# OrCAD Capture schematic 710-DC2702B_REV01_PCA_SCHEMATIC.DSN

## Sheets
1 PAGE1: size Custom
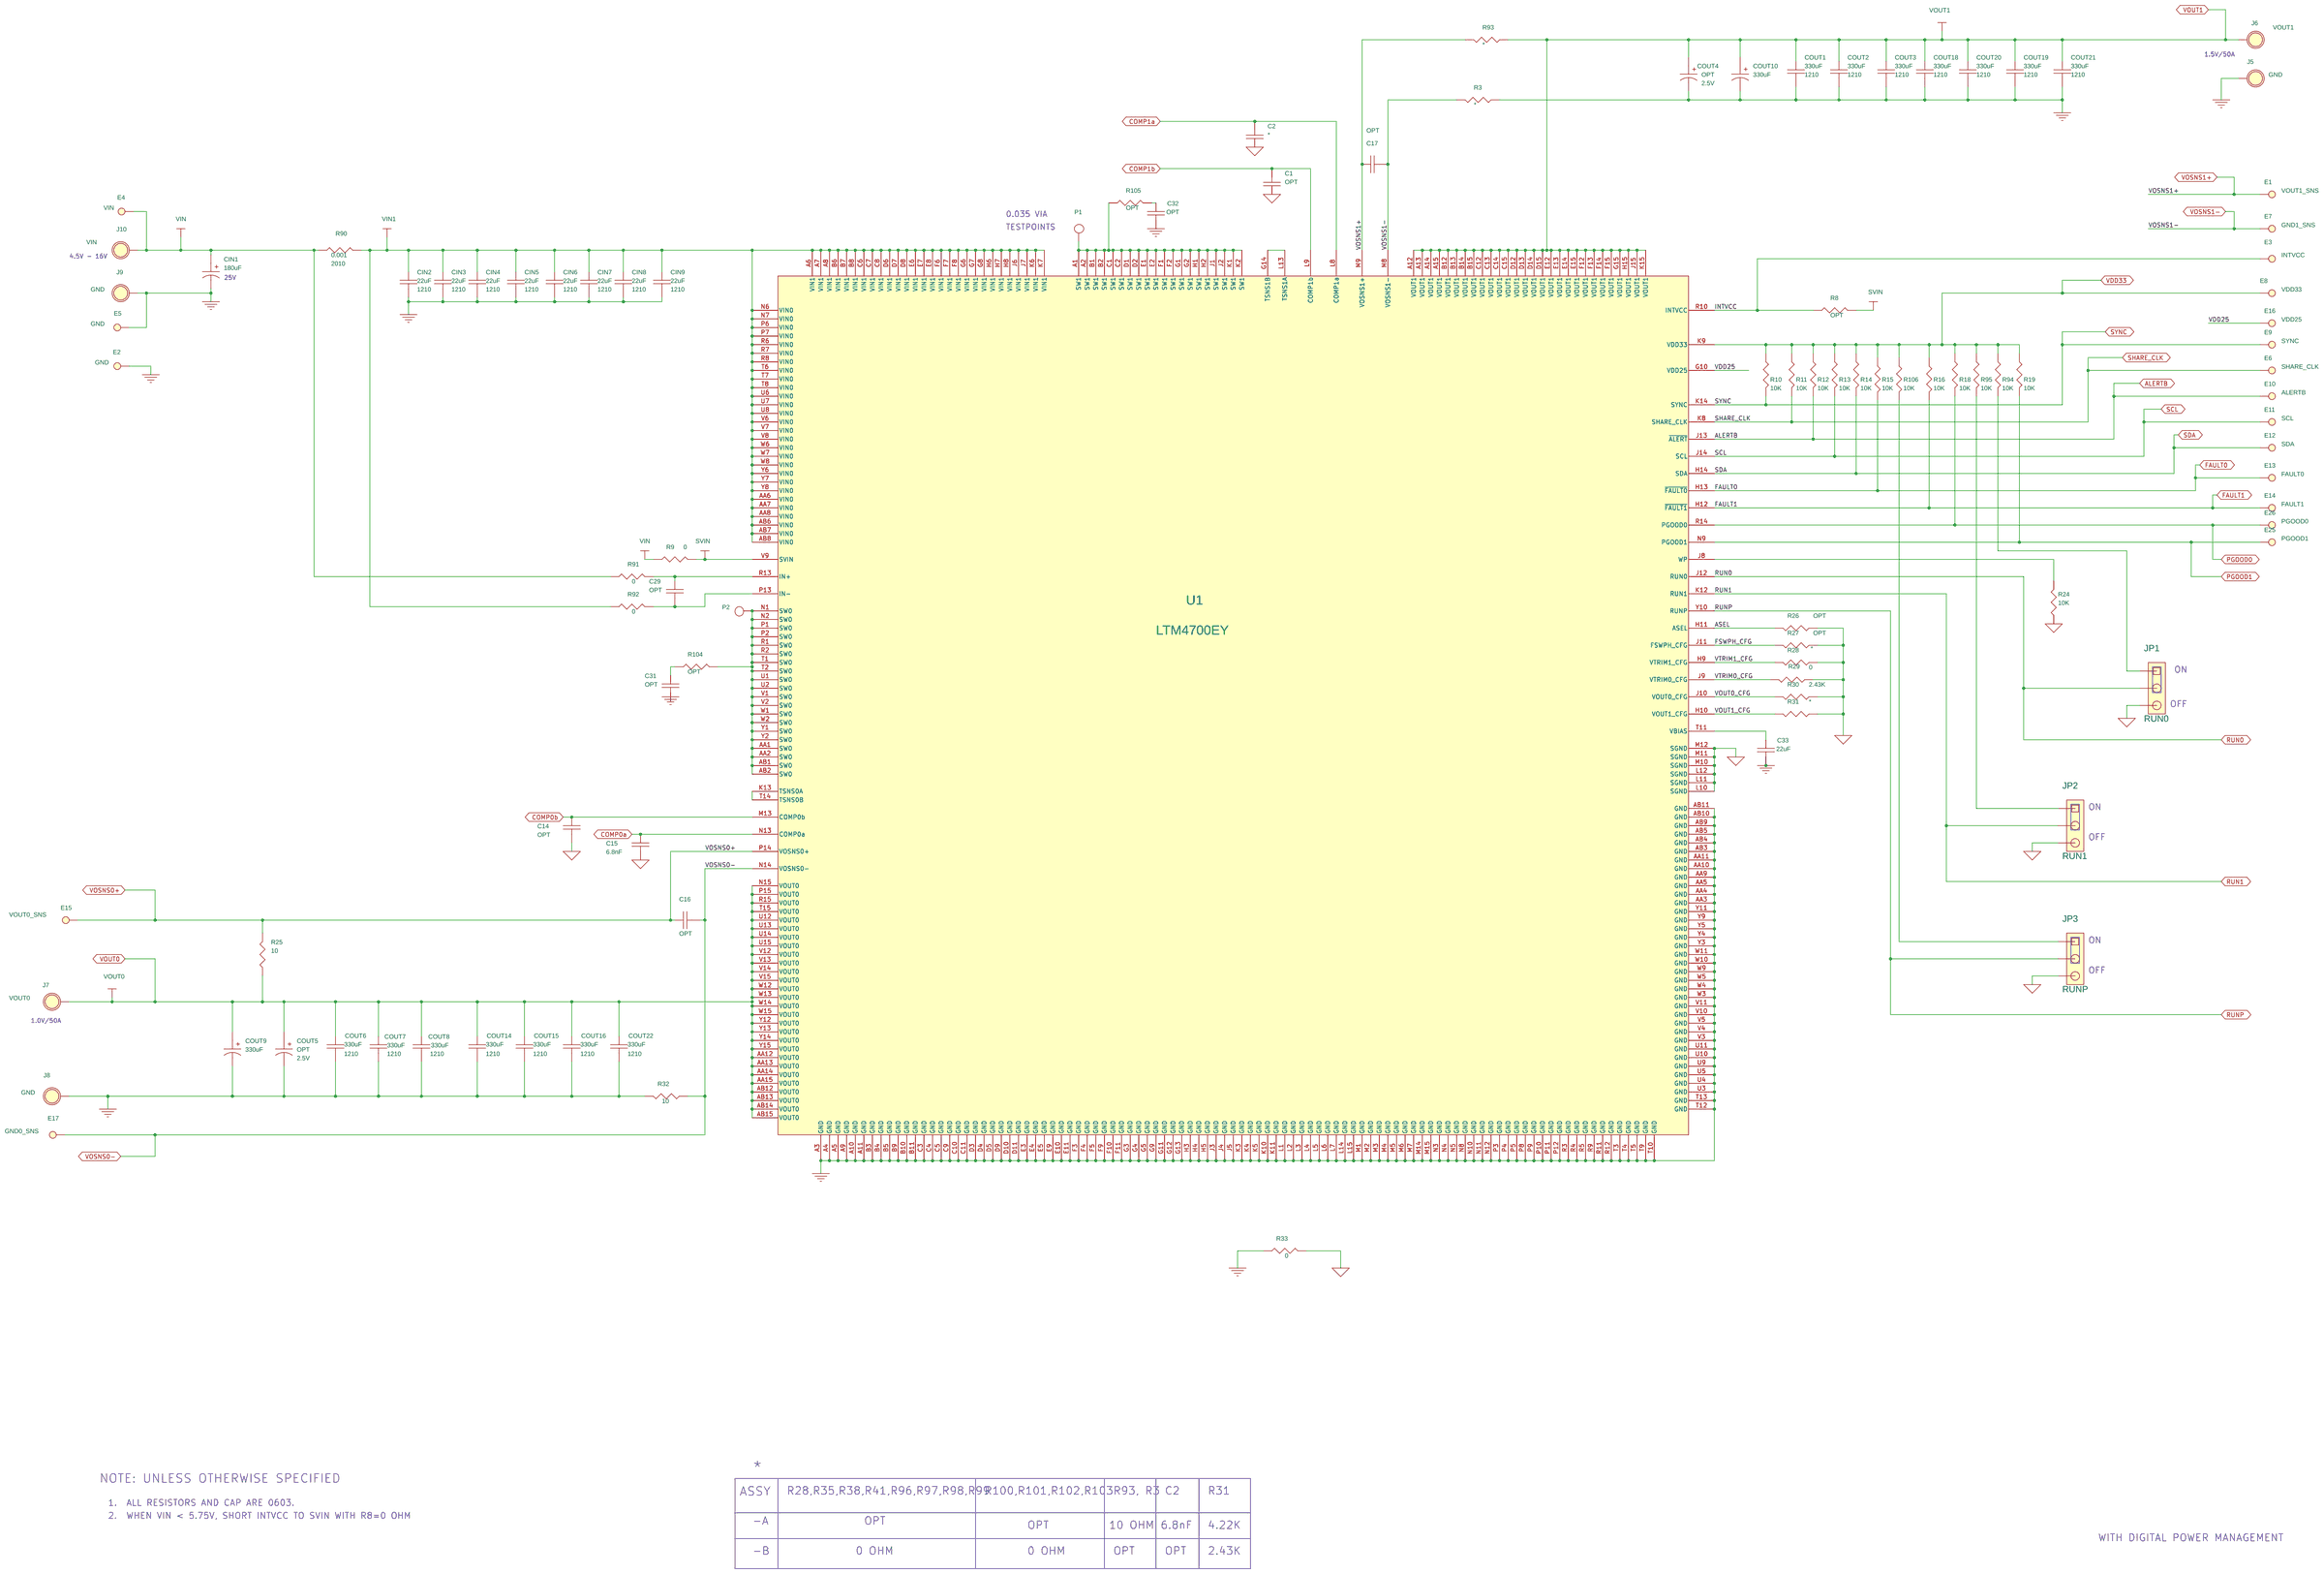
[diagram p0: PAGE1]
2 PAGE3: size B; title: CONTROLLER with GaN FET; company: ANALOG DEVICES; note: DEMO BOARD BILL OF MATERIALS; note: DUAL 50A OR SINGLE 100A uMODULE REGULATOR
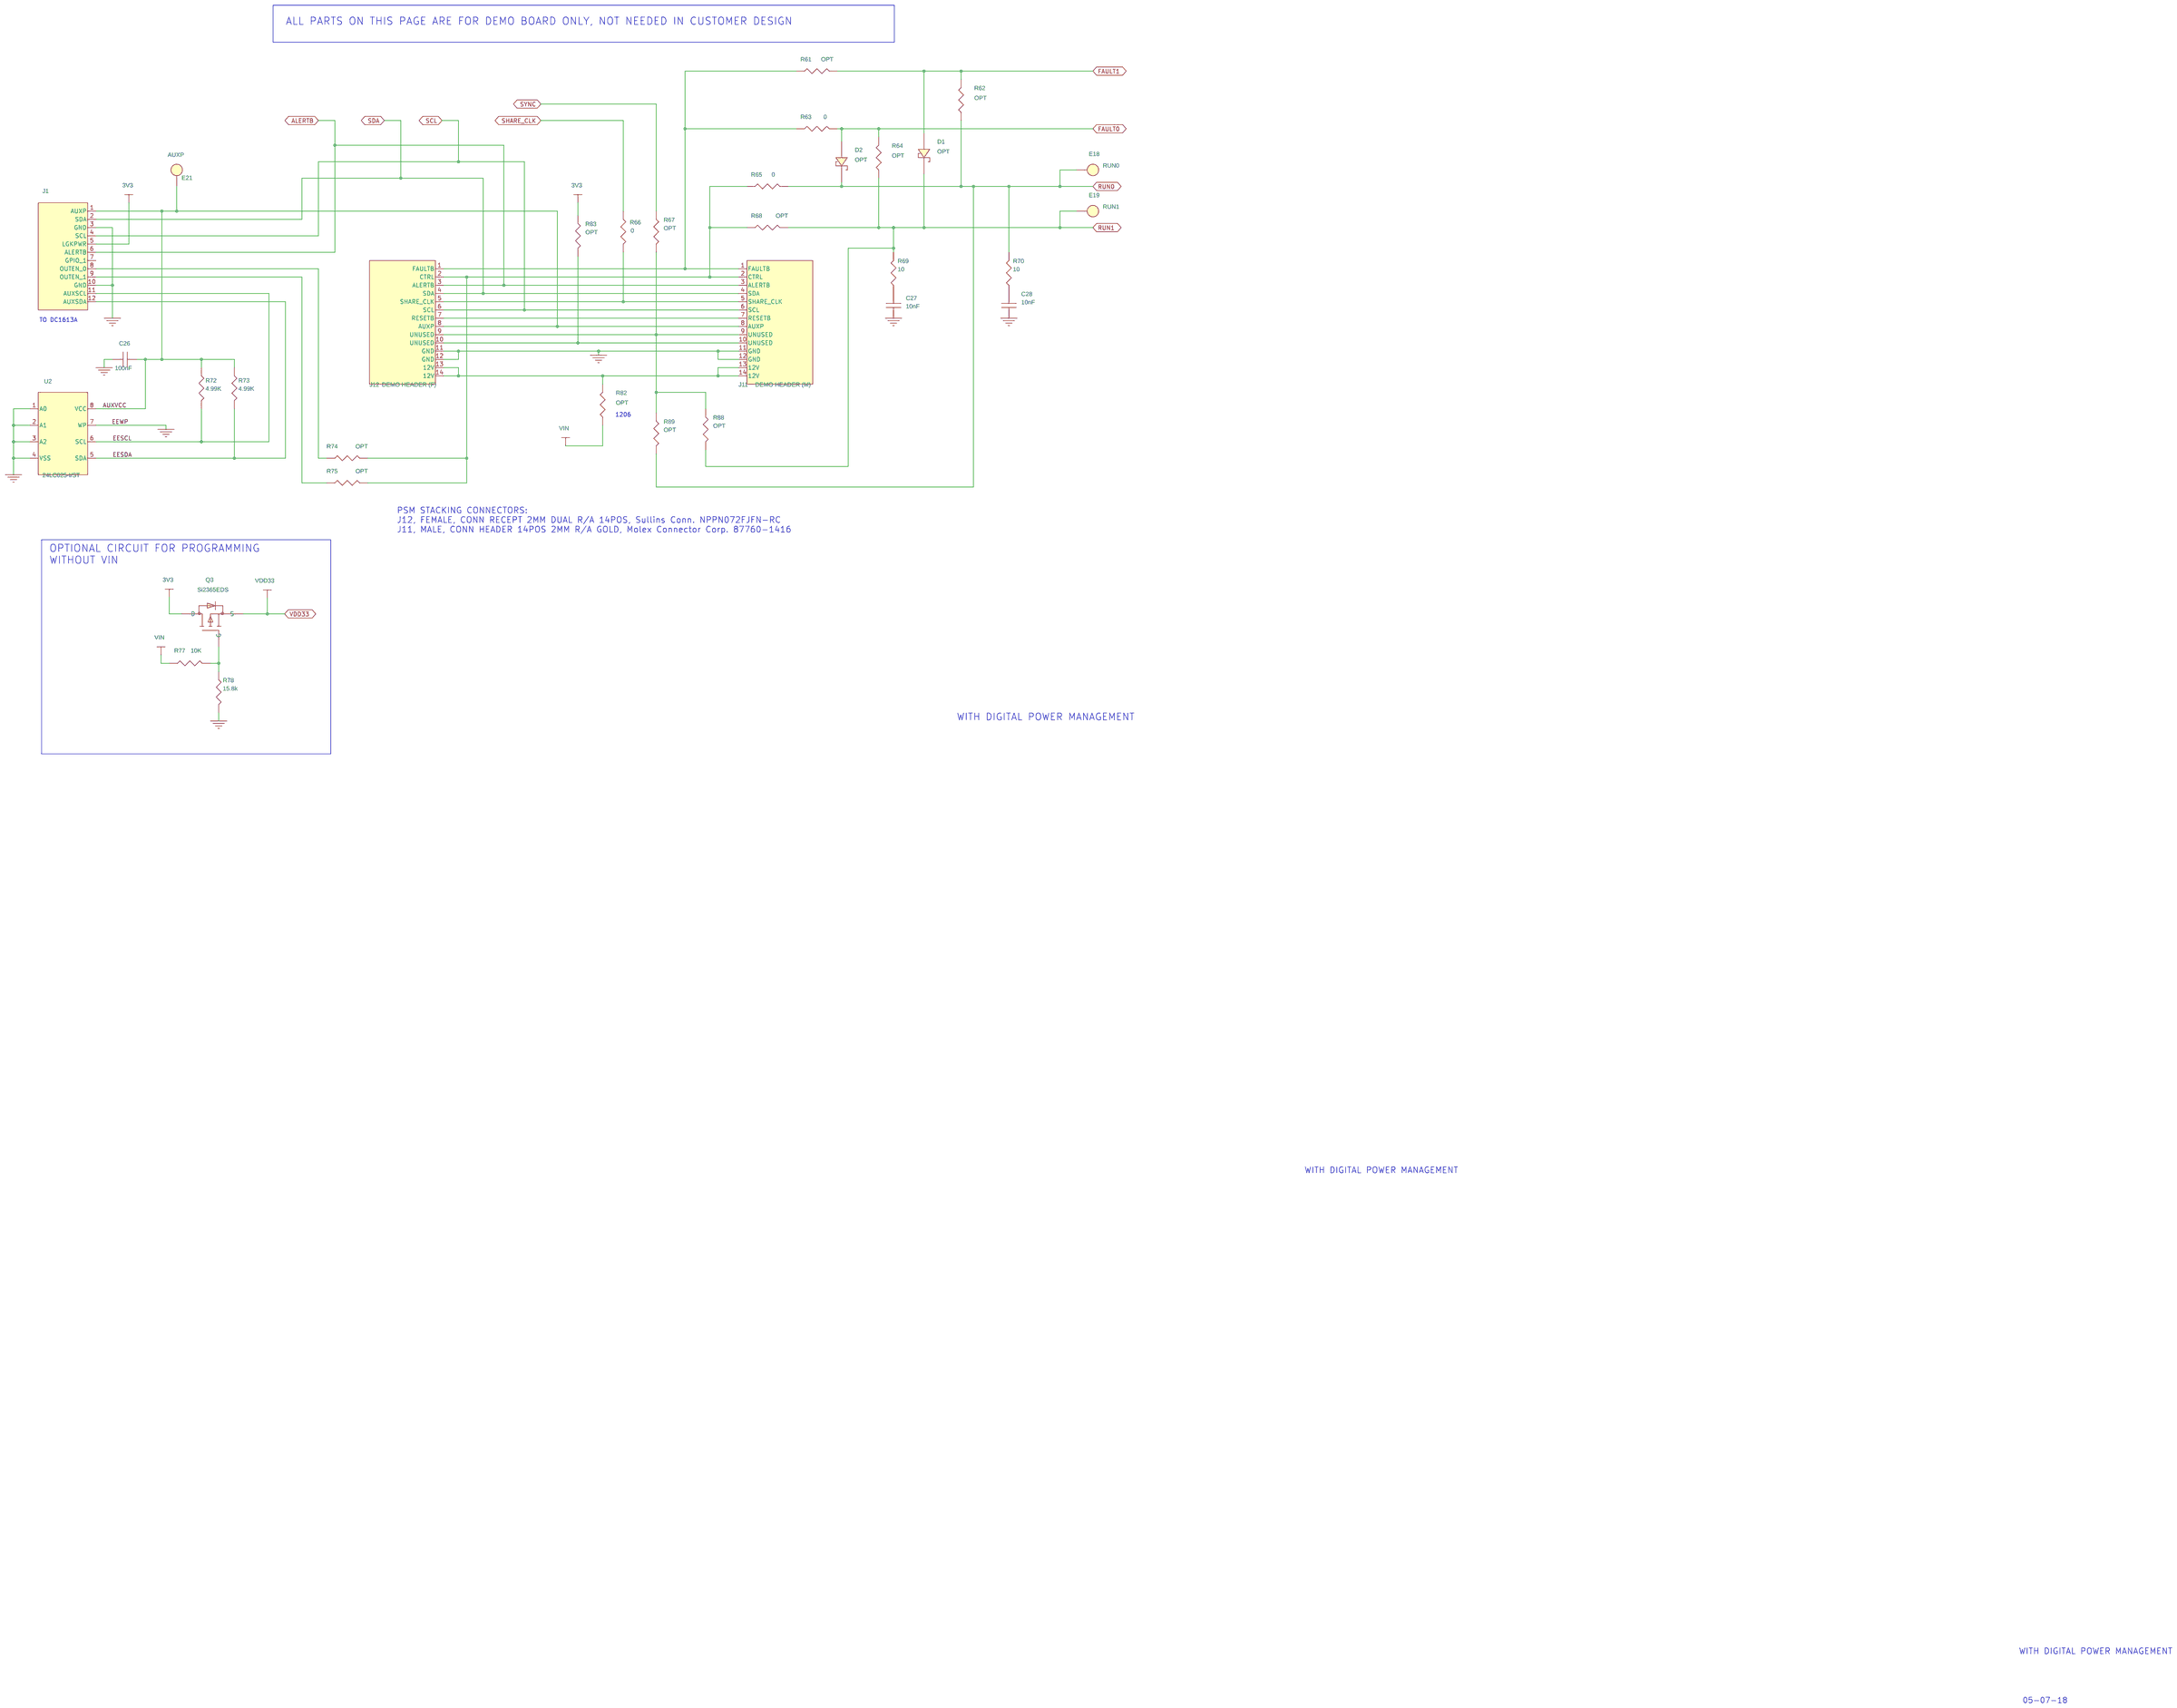
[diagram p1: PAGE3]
3 PAGE2: size Custom; title: CONTROLLER with GaN FET; company: ANALOG DEVICES; note: DEMO BOARD BILL OF MATERIALS; note: DUAL 50A OR SINGLE 100A uMODULE REGULATOR
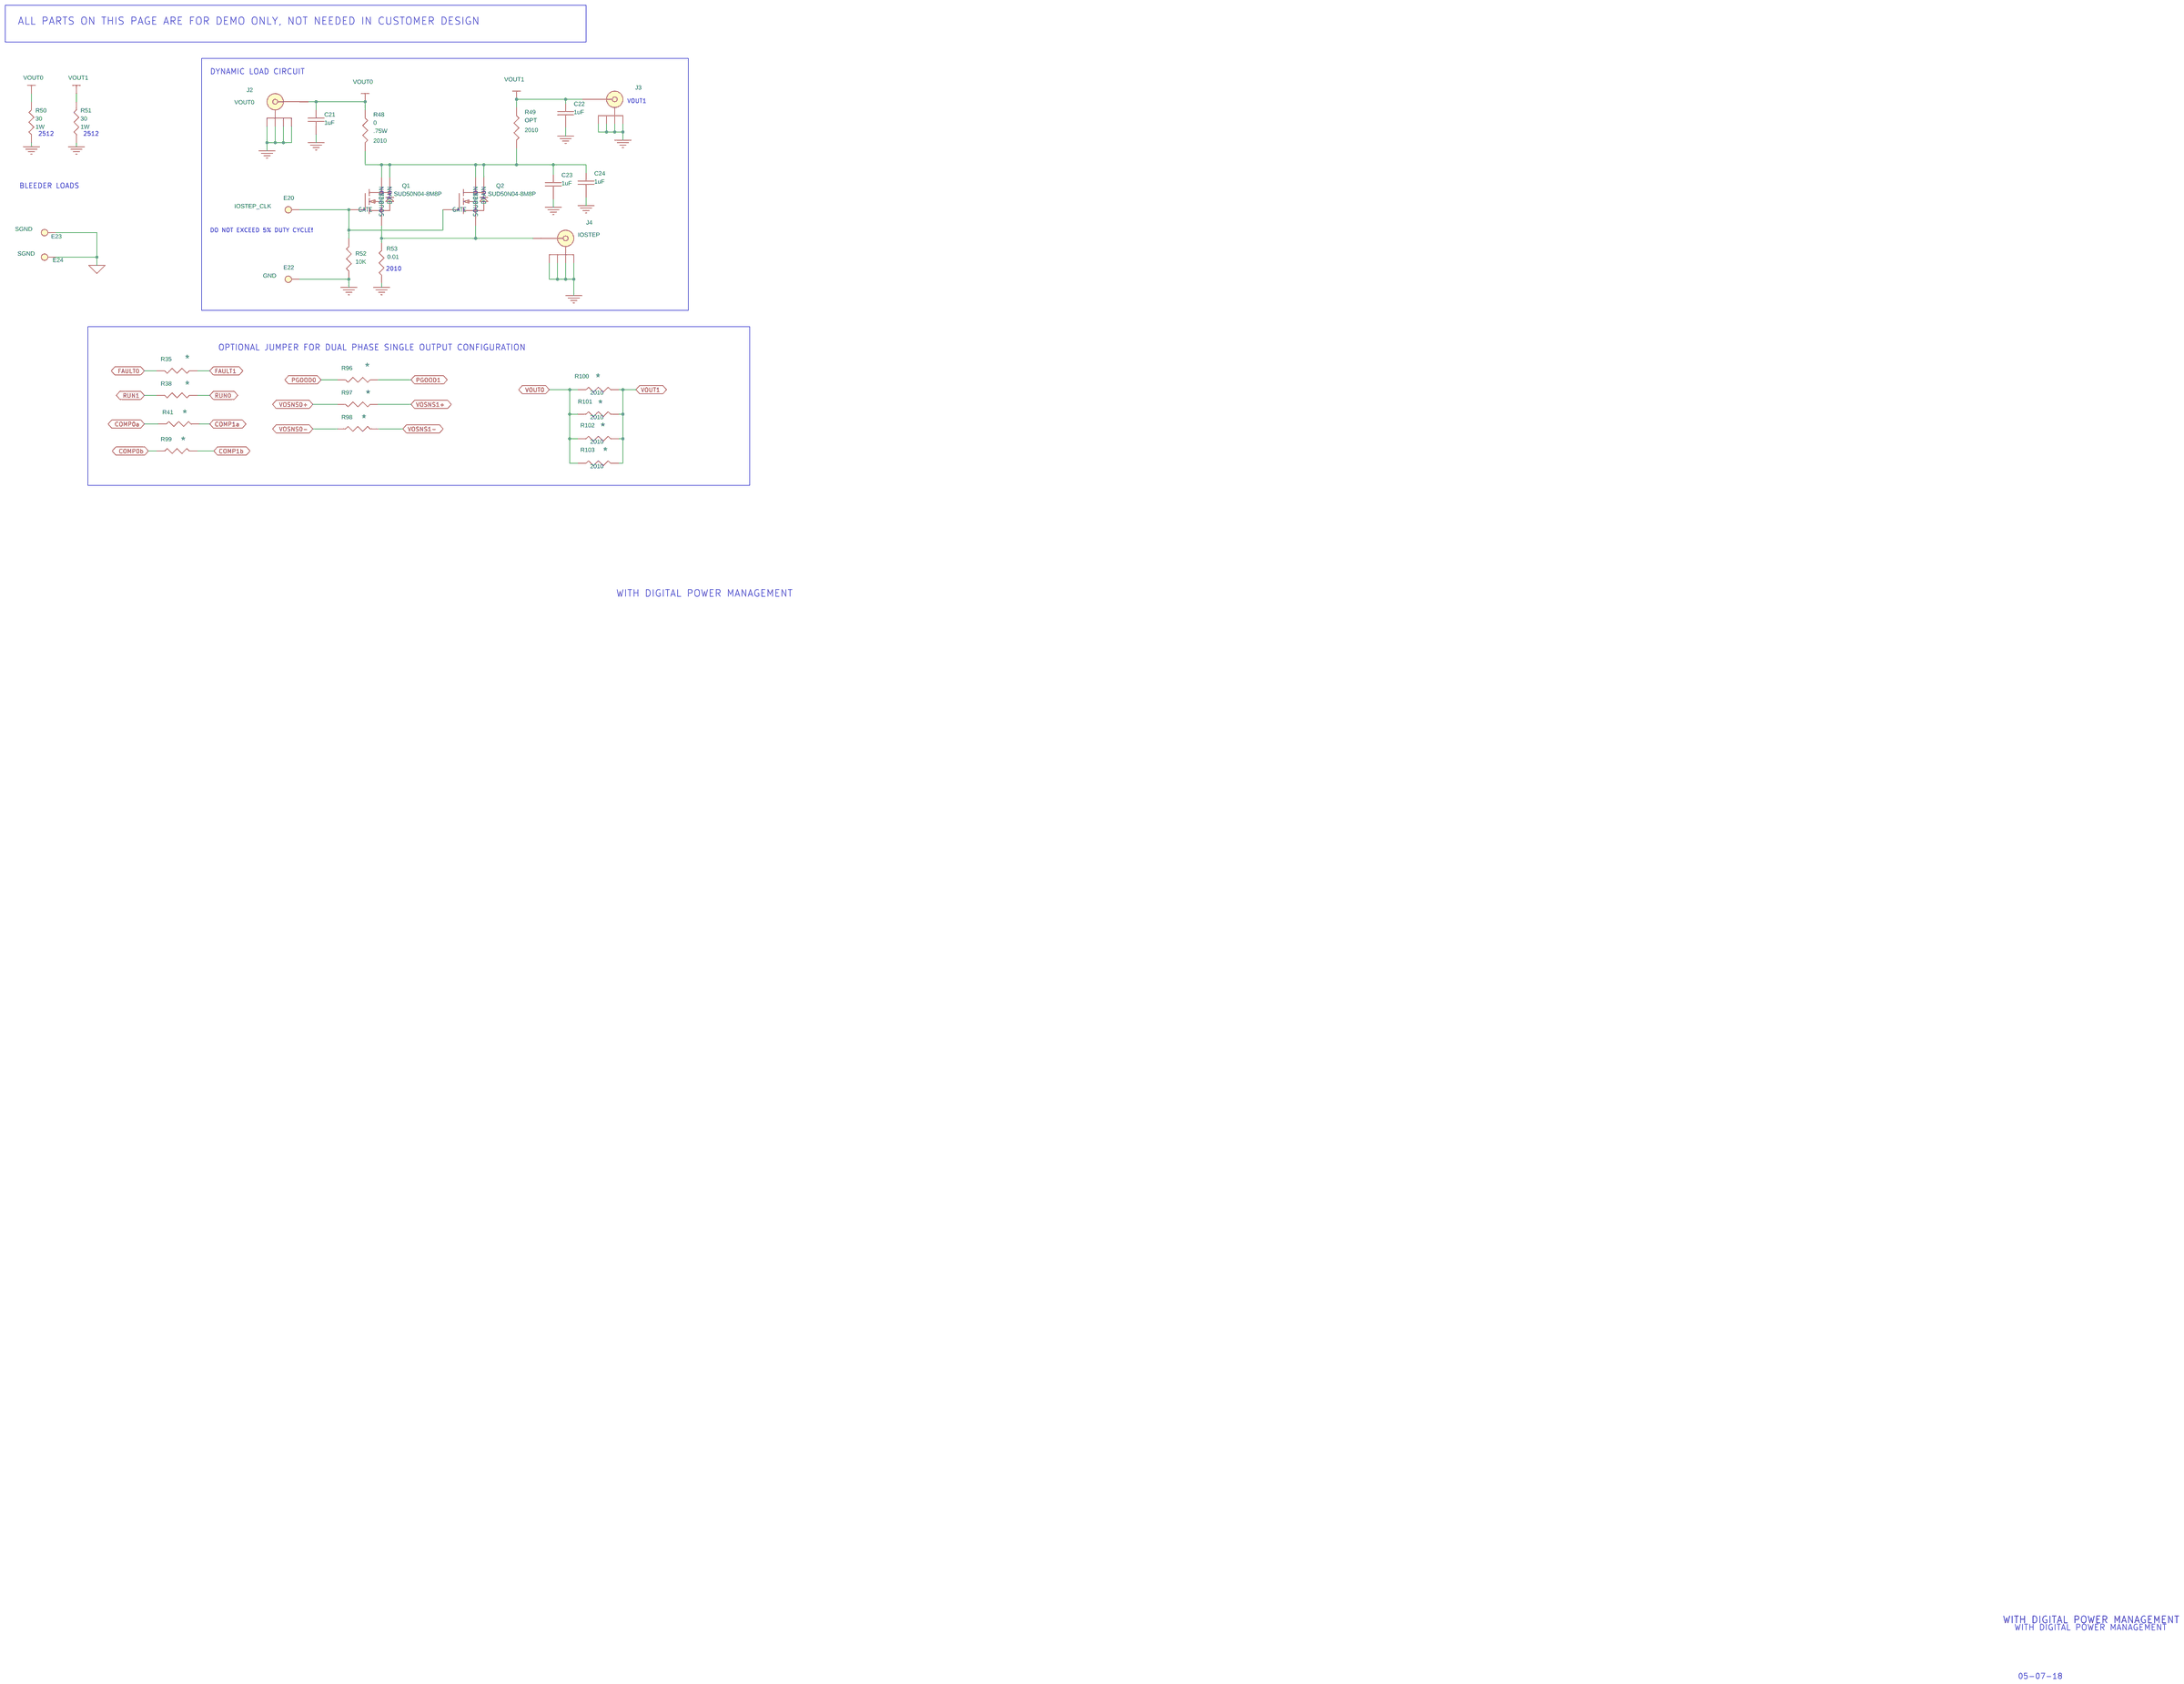
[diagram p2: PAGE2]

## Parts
sheet PAGE1
C1  OPT  [0603XS]
C2  *  [0603XS]
C14  OPT  [0603XS]
C15  6.8nF  [0603XS]
C16  OPT  [0603]
C17  OPT  [0603]
C29  OPT  [0603XS]
C31  OPT  [0603]
C32  OPT  [0603]
C33  22uF  [0603XS]
CIN1  180uF  [SANYO\8X10]
CIN2  22uF  [1210]
CIN3  22uF  [1210]
CIN4  22uF  [1210]
CIN5  22uF  [1210]
CIN6  22uF  [1210]
CIN7  22uF  [1210]
CIN8  22uF  [1210]
CIN9  22uF  [1210]
COUT1  330uF  [1210]
COUT2  330uF  [1210]
COUT3  330uF  [1210]
COUT4  OPT  [D3L]
COUT5  OPT  [D3L]
COUT6  330uF  [1210]
COUT7  330uF  [1210]
COUT8  330uF  [1210]
COUT9  330uF  [D3L]
COUT10  330uF  [D3L]
COUT14  330uF  [1210]
COUT15  330uF  [1210]
COUT16  330uF  [1210]
COUT18  330uF  [1210]
COUT19  330uF  [1210]
COUT20  330uF  [1210]
COUT21  330uF  [1210]
COUT22  330uF  [1210]
E1  TURRETS  [TURRETS]
E2  GND  [TURRETS]
E3  INTVCC  [TURRETS]
E4  TURRETS  [TURRETS]
E5  GND  [TURRETS]
E6  TURRETS  [TURRETS]
E7  TURRETS  [TURRETS]
E8  VDD33  [TURRETS]
E9  TURRETS  [TURRETS]
E10  TURRETS  [TURRETS]
E11  TURRETS  [TURRETS]
E12  TURRETS  [TURRETS]
E13  TURRETS  [TURRETS]
E14  TURRETS  [TURRETS]
E15  TURRETS  [TURRETS]
E16  VDD25  [TURRETS]
E17  TURRETS  [TURRETS]
E25  TURRETS  [TURRETS]
E26  TURRETS  [TURRETS]
J5  BANANA SMALL  [CON\LUG\10]
J6  BANANA SMALL  [CON\LUG\10]
J7  BANANA SMALL  [CON\LUG\10]
J8  BANANA SMALL  [CON\LUG\10]
J9  BANANA SMALL  [CON\LUG\10]
J10  BANANA SMALL  [CON\LUG\10]
JP1  3 Pins 2mm Ctrs.  [HD1X3-079]
JP2  3 Pins 2mm Ctrs.  [HD1X3-079]
JP3  3 Pins 2mm Ctrs.  [HD1X3-079]
P1  TURRETS  [PAD]
P2  TURRETS  [PAD]
R3  *  [0603]
R8  OPT  [0603XS]
R9  0  [0603XS]
R10  10K  [0603]
R11  10K  [0603]
R12  10K  [0603]
R13  10K  [0603]
R14  10K  [0603]
R15  10K  [0603]
R16  10K  [0603]
R18  10K  [0603]
R19  10K  [0603]
R24  10K  [0603]
R25  10  [0603]
R26  OPT  [0603]
R27  OPT  [0603]
R28  *  [0603]
R29  0  [0603]
R30  2.43K  [0603]
R31  *  [0603]
R32  10  [0603]
R33  0  [0603XS]
R90  0.001  [2010]
R91  0  [0603XS]
R92  0  [0603XS]
R93  *  [0603]
R94  10K  [0603]
R95  10K  [0603]
R104  OPT  [0805]
R105  OPT  [0805]
R106  10K  [0603]
U1  LTM4700EY  [LTC-BGA-330-1568]
sheet PAGE2
C21  1uF  [0603]
C22  1uF  [0603]
C23  1uF  [0805]
C24  1uF  [0603]
E20  IOSTEP_CLK  [TURRETS]
E22  GND  [TURRETS]
E23  SGND  [TURRETS]
E24  SGND  [TURRETS]
J2  VOUT0  [BNC]
J3  XXX  [BNC]
J4  IOSTEP  [BNC]
Q1  SUD50N04-8M8P  [TO252]
Q2  SUD50N04-8M8P  [TO252]
R35  *  [0603]
R38  *  [0603]
R41  *  [0603XS]
R48  0  [2010]
R49  OPT  [2010]
R50  30  [2512SENSE]
R51  30  [2512SENSE]
R52  10K  [0603]
R53  0.01  [2010]
R96  *  [0603]
R97  *  [0603]
R98  *  [0603]
R99  *  [0603]
R100  *  [2010]
R101  *  [2010]
R102  *  [2010]
R103  *  [2010]
sheet PAGE3
C26  100nF  [0603]
C27  10nF  [0603]
C28  10nF  [0603]
D1  OPT  [SOD323]
D2  OPT  [SOD323]
E18  RUN0  [TURRETS]
E19  RUN1  [TURRETS]
E21  AUXP  [TURRETS]
J1  HD2X6-079  [HD2X6-079-MOLEX]
J11  DEMO HEADER (M)  [NPPN072FJFN]
J12  DEMO HEADER (F)  [NPPN072FJFN-RC]
Q3  Si2365EDS  [SOT-23]
R61  OPT  [0603]
R62  OPT  [0603]
R63  0  [0603]
R64  OPT  [0603]
R65  0  [0603]
R66  0  [0603]
R67  OPT  [0603]
R68  OPT  [0603]
R69  10  [0603]
R70  10  [0603]
R72  4.99K  [0603]
R73  4.99K  [0603]
R74  OPT  [0603]
R75  OPT  [0603]
R77  10K  [0603]
R78  15.8k  [0603]
R82  OPT  [1206]
R83  OPT  [0603]
R88  OPT  [0603]
R89  OPT  [0603]
U2  24LC025-I/ST  [TSSOP-8_4.4MM]

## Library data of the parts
C1 C2 C14-C17 C29 C31-C33 = CAP0603_1: Component: cap; Manufacturer: TDK; Manufacturer P/N: C1608C0G1H102J; Tolerance: 5%; Type: cer 0603; Vendor: Digikey; Vendor P/N: 445-1293-1-ND; Volts/Amps/Watts: 50V
CIN1 = CAPR12X5_0: Component: cap; Manufacturer: SANYO; Tolerance: 20%; Type: OS-CON; Volts/Amps/Watts: 16V
CIN2-CIN9 = CAP1210_1: Component: cap; Manufacturer: Taiyo Yuden; Manufacturer P/N: GMK325BJ106KN-T; Tolerance: 10%; Type: cer 1210; Vendor: Digikey; Vendor P/N: 587-1439-1-ND; Volts/Amps/Watts: 35V
COUT1 COUT18 = CAP0603_1: Component: cap; Manufacturer: TDK; Manufacturer P/N: C3225X5R0J107M; Tolerance: 20%; Type: cer 1210 X5R; Vendor: Digikey; Vendor P/N: 445-1437-1-ND; Volts/Amps/Watts: 6.3v
COUT2 COUT3 COUT6-COUT8 COUT14-COUT16 COUT19-COUT22 = CAP0603_1: Component: cap; Manufacturer: TDK; Manufacturer P/N: C3225X5R0J107M; Part Type: CAP1210; Tolerance: 20%; Type: cer 1210 X5R; Vendor: Digikey; Vendor P/N: 445-1437-1-ND; Volts/Amps/Watts: 6.3v
COUT4 COUT5 COUT9 COUT10 = CAPR12X5_0: Component: cap; Manufacturer: SANYO; Manufacturer P/N: EEFGX0E471R; Tolerance: 20%; Type: SP-CAP; Volts/Amps/Watts: 2.5V
E1 = TURRETS_1: Component: tp; Label: VOUT1_SNS; Vendor: Digikey; Vendor P/N: 1593-2K-ND
E2 E5 E22 = TURRETS_1: Component: tp; Manufacturer: Keystone; Manufacturer P/N: 1593-2; Vendor: Digikey; Vendor P/N: 1593-2K-ND
E3 E8 E16 E20 E23 E24 = TURRETS_1: Component: tp; Label: GND; Manufacturer: Keystone; Manufacturer P/N: 1593-2; Vendor: Digikey; Vendor P/N: 1593-2K-ND
E4 = TURRETS_1: Component: tp; Label: VIN; Manufacturer: Keystone; Manufacturer P/N: 1593-2; Vendor: Digikey; Vendor P/N: 1593-2K-ND
E6 = TURRETS_1: Component: tp; Label: SHARE_CLK; Manufacturer: Keystone; Manufacturer P/N: 1593-2; Vendor: Digikey; Vendor P/N: 1593-2K-ND
E7 = TURRETS_1: Component: tp; Label: GND1_SNS; Vendor: Digikey; Vendor P/N: 1593-2K-ND
E9 = TURRETS_1: Component: tp; Label: SYNC; Manufacturer: Keystone; Manufacturer P/N: 1593-2; Vendor: Digikey; Vendor P/N: 1593-2K-ND
E10 = TURRETS_1: Component: tp; Label: ALERTB; Manufacturer: Keystone; Manufacturer P/N: 1593-2; Vendor: Digikey; Vendor P/N: 1593-2K-ND
E11 = TURRETS_1: Component: tp; Label: SCL; Manufacturer: Keystone; Manufacturer P/N: 1593-2; Vendor: Digikey; Vendor P/N: 1593-2K-ND
E12 = TURRETS_1: Component: tp; Label: SDA; Manufacturer: Keystone; Manufacturer P/N: 1593-2; Vendor: Digikey; Vendor P/N: 1593-2K-ND
E13 = TURRETS_1: Component: tp; Label: FAULT0; Manufacturer: Keystone; Manufacturer P/N: 1593-2; Vendor: Digikey; Vendor P/N: 1593-2K-ND
E14 = TURRETS_1: Component: tp; Label: FAULT1; Manufacturer: Keystone; Manufacturer P/N: 1593-2; Vendor: Digikey; Vendor P/N: 1593-2K-ND
E15 = TURRETS_1: Component: tp; Label: VOUT0_SNS; Vendor: Digikey; Vendor P/N: 1593-2K-ND
E17 = TURRETS_1: Component: tp; Label: GND0_SNS; Vendor: Digikey; Vendor P/N: 1593-2K-ND
E25 = TURRETS_1: Component: tp; Label: PGOOD1; Manufacturer: Keystone; Manufacturer P/N: 1593-2; Vendor: Digikey; Vendor P/N: 1593-2K-ND
E26 = TURRETS_1: Component: tp; Label: PGOOD0; Manufacturer: Keystone; Manufacturer P/N: 1593-2; Vendor: Digikey; Vendor P/N: 1593-2K-ND
J5 J8 J9 = BANANA_SMALL_0: Component: conn; Label: GND
J6 = BANANA_SMALL_0: Component: conn; Label: VOUT1
J7 = BANANA_SMALL_0: Component: conn; Label: VOUT0
J10 = BANANA_SMALL_0: Component: conn; Label: VIN
JP1 = Commcon2802s03g2_7: 11th Part Field: OFF; 12th Part Field: RUN0; 9th Part Field: ON
JP2 = Commcon2802s03g2_7: 11th Part Field: OFF; 12th Part Field: RUN1; 9th Part Field: ON
JP3 = Commcon2802s03g2_7: 11th Part Field: OFF; 12th Part Field: RUNP; 9th Part Field: ON
P1 P2 = PAD_2: Component: tp; Label: <Label>; Vendor: Digikey; Vendor P/N: 1593-2K-ND
R3 = RES0603_9: Label: 0; Manufacturer: Rohm; Manufacturer P/N: RHM0.0GCT-ND; Tolerance: 5%; Vendor: Digikey; Vendor P/N: RHM0.0GCT-ND; Volts/Amps/Watts: 0.1W
R8 = RES0603_9: Label: OPT 0; Manufacturer: Rohm; Manufacturer P/N: RHM0.0GCT-ND; Vendor: Digikey
R9 R33 R41 R98 R99 = RES0603_3
R10-R16 R18 R19 R24 R29 R30 R91 R92 R94 R95 R104-R106 = RES0603_9: Manufacturer: ROHM; Manufacturer P/N: MCR03EZPFX1002; Vendor: Digikey; Vendor P/N: RHM10.0KHCT-ND; Volts/Amps/Watts: 0.1W
R25 = RES0603_9: Manufacturer: Rohm; Manufacturer P/N: MCR03EZPFX1000; Vendor: Digikey; Vendor P/N: RHM100HCT-ND; Volts/Amps/Watts: 0.1W
R26 R27 = RES0603_9: Manufacturer: Panasonic; Manufacturer P/N: ERJ-3EKF2002V; Vendor: Digikey; Vendor P/N: P20.0KHCT-ND; Volts/Amps/Watts: 0.1W
R28 = RES0603_9: Manufacturer: Panasonic; Manufacturer P/N: ERJ-3EKF1000V; Vendor: Digikey; Vendor P/N: P100HCT-ND; Volts/Amps/Watts: 0.1W
R31 = RES0603_9: Manufacturer: Panasonic; Manufacturer P/N: ERJ-3EKF1021V; Vendor: Digikey; Vendor P/N: P1.02KHCT-ND; Volts/Amps/Watts: 0.1W
R32 = RES0603_9: Manufacturer: Yageo; Manufacturer P/N: RC0603JR-070RL; Tolerance: 5%; Vendor: Digikey; Vendor P/N: 311-0.0GRCT-ND; Volts/Amps/Watts: 0.1W
R90 R100-R103 = RES2512_0: Tolerance: <Tolerance>
R93 = RES0603_9: Manufacturer: Rohm; Manufacturer P/N: RHM0.0GCT-ND; Tolerance: 5%; Vendor: Digikey; Vendor P/N: RHM0.0GCT-ND; Volts/Amps/Watts: 0.1W
U1 = LTC3880-M0001_58: Component: IC; Manufacturer: LTC; Manufacturer P/N: LTC3880_M0001; Vendor: LTC; Vendor P/N: LTC3880_M0001
C21 C22 C24 = CAP0603_1
C23 = CAP1206_1: Manufacturer: Kemet; Manufacturer P/N: C1206C106K8RACTU; Tolerance: 10%; Type: cer 1206 X7R; Vendor: Digikey; Vendor P/N: 399-4937-1-ND; Volts/Amps/Watts: 10V
J2 J4 = BNC5-SCH_0
J3 = BNC5-SCH_0: CONN,BNC,5 PINS; Part Number: CONNEX 112404
Q1 Q2 = IRF540_0
R35 R38 R96 R97 = RES0603_9: Label: OPT 0; Manufacturer: Rohm; Manufacturer P/N: RHM0.0GCT-ND; Tolerance: 5%; Vendor: Digikey; Vendor P/N: RHM0.0GCT-ND; Volts/Amps/Watts: 0.1W
R48 = RES2512_0: Volts/Amps/watts: .75W
R49 = RES2512_0
R50 = RES0603_5: Label: 1W; Manufacturer: VISHAY; Manufacturer P/N: CRCW251230R0JNEG; Tolerance: 5%; Vendor: Digikey; Vendor P/N: 541-30XCT-ND; Volts/Amps/Watts: 0.1W
R51 = RES0603_6: Label: 1W; Tolerance: 5%; Vendor: Digikey; Vendor P/N: 541-30XCT-ND; Volts/Amps/Watts: 0.1W
R52 = RES0603_9
R53 = RES0603_5: Label: 1W; Manufacturer: VISHAY; Manufacturer P/N: CRCW251230R0JNEG; Part Type: 2512; Tolerance: 5%; Vendor: Digikey; Vendor P/N: 541-30XCT-ND; Volts/Amps/Watts: 0.1W
C26 = CAP_NP: CAP, 0603 100nF 20% 16V X7R; Part Number: AVX 0603YC104MAT2A
C27 C28 = CAP_NP: CAP, 0603 10nF 10% 25V X7R; Part Number: AVX 06033C103KAT2A
D1 D2 = DIODE_SCHOTTKY_9: DIODE, SCHOTTKY 30V, 100mA; Part Number: CENTRAL SEMI CMDSH-3-TR
E18 E19 E21 = E_0: TURRET; Part Number: MILL MAX 2501-2-00-80-00-00-07-0
J1 = HD2X6-079-PMBUS_2: HEADER, 12PIN 2mm STR DL; Label: DC1427A HEADER; Manufacturer: MOLEX; Manufacturer P/N: 87831-1220; Part Number: FCI 98414-G06-12ULF; Type: header 12POS 2MM VERT; Vendor: Digikey; Vendor P/N: WM18561-ND
J11 = PMBUS_CONNECTOR20_3: CONN, SOCKET 20PIN  DUAL ROW R/A; Component: con; Manufacturer: Mill Max; Manufacturer P/N: 803-93-020-20-001; Part Number: MILL MAX 803-93-020-20-001; Type: conn  RA 20 dual row; Vendor: LTC; Vendor P/N: 803-93-020-20-001
J12 = PMBUS_HEADER20_3: HEADER, 20PIN DUAL ROW R/A; Component: con; Manufacturer: Mill Max; Manufacturer P/N: 802-40-020-20-0001; Part Number: MILL MAX 802-40-020-20-0001; Type: header RA 20 dual row; Vendor: LTC; Vendor P/N: 802-40-020-20-001
Q3 = P-MOSFET: XSTR, N-CHANNEL DMOS FET; Part Number: VISHAY TP0101K-T1-E3
R61 R63 R65 R68 = RES0603_0: RES, 0603 0 OHMS JUMPER; Label: OPT 0; Manufacturer: Rohm; Manufacturer P/N: RHM0.0GCT-ND; Part Number: VISHAY CRCW06030000Z0EA; Tolerance: 5%; Vendor: Digikey; Vendor P/N: RHM0.0GCT-ND; Volts/Amps/Watts: 0.1W
R62 R64 R67 R75 R83 R88 R89 = RES0603_0: RES, 0603 OPTION; Label: OPT 0; Manufacturer: Rohm; Manufacturer P/N: RHM0.0GCT-ND; Part Number: OPTION; Tolerance: 5%; Vendor: Digikey; Vendor P/N: RHM0.0GCT-ND; Volts/Amps/Watts: 0.1W
R66 = RES0603_0: RES, 0603 0 OHMS JUMPER; Manufacturer: Rohm; Manufacturer P/N: RHM0.0GCT-ND; Part Number: VISHAY CRCW06030000Z0EA; Tolerance: 5%; Vendor: Digikey; Vendor P/N: RHM0.0GCT-ND; Volts/Amps/Watts: 0.1W
R69 R70 = RES0603_1: RES, 0603 10 OHMS 5% 1/10W; Manufacturer: Rohm; Manufacturer P/N: RHM0.0GCT-ND; Part Number: VISHAY CRCW060310R0JNEA; Tolerance: 5%; Vendor: Digikey; Vendor P/N: RHM0.0GCT-ND; Volts/Amps/Watts: 0.1W
R72 R73 = RES0603_0: RES, 0603 4.99K OHMS 1% 1/10W; Manufacturer: ROHM; Manufacturer P/N: MCR03EZPFX4991; Part Number: VISHAY CRCW06034K99FKEA; Vendor: Digikey; Vendor P/N: RHM4.99KHCT-ND; Volts/Amps/Watts: 0.1w
R74 R82 = RES0603_3: RES, 0603 OPTION; Label: OPT 0; Manufacturer: Rohm; Manufacturer P/N: RHM0.0GCT-ND; Part Number: OPTION; Tolerance: 5%; Vendor: Digikey; Vendor P/N: RHM0.0GCT-ND; Volts/Amps/Watts: 0.1W
R77 = RES0603_11: RES, 0603 10K OHMS 5% 1/10W; Part Number: VISHAY CRCW060310K0JNEA
R78 = RES0603_11: RES, 0603 15.8K OHMS 1% 1/10W; Part Number: VISHAY CRCW060315K8FKEA
U2 = 24LC025-I_SN: IC, 24LC05-I/ST; Part Number: MICROCHIP 24LC025-I/ST

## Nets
3V3: J1.5(LGKPWR) Q3.3(D) R83.1
GND_POWER: C21.2 C22.2 C23.2 C24.2 C26.2 C27.2 C28.2 C31.2 C32.2 C33.2 CIN1.2 CIN2.2 CIN3.2 CIN4.2 CIN5.2 CIN6.2 CIN7.2 CIN8.2 CIN9.2 COUT1.2 COUT2.2 COUT3.2 COUT4.2 COUT5.2 COUT6.2 COUT7.2 COUT8.2 COUT9.2 COUT10.2 COUT14.2 COUT15.2 COUT16.2 COUT18.2 COUT19.2 COUT20.2 COUT21.2 COUT22.2 E2.1(TP) E5.1(TP) E22.1(TP) J1.3(GND) J1.10(GND) J2.2 J2.3 J2.4 J2.5 J3.2 J3.3 J3.4 J3.5 J4.2 J4.3 J4.4 J4.5 J5.1(TP) J8.1(TP) J9.1(TP) J11.11(GND) J11.12(GND) J12.11(GND) J12.12(GND) R3.2 R32.2 R33.1 R50.1 R51.1 R52.2 R53.1 R78.2 U1.A3(GND) U1.A4(GND) U1.A5(GND) U1.A9(GND) U1.A10(GND) U1.A11(GND) U1.AA3(GND) U1.AA4(GND) U1.AA5(GND) U1.AA9(GND) U1.AA10(GND) U1.AA11(GND) U1.AB3(GND) U1.AB4(GND) U1.AB5(GND) U1.AB9(GND) U1.AB10(GND) U1.AB11(GND) U1.B3(GND) U1.B4(GND) U1.B5(GND) U1.B9(GND) U1.B10(GND) U1.B11(GND) U1.C3(GND) U1.C4(GND) U1.C5(GND) U1.C9(GND) U1.C10(GND) U1.C11(GND) U1.D3(GND) U1.D4(GND) U1.D5(GND) U1.D9(GND) U1.D10(GND) U1.D11(GND) U1.E3(GND) U1.E4(GND) U1.E5(GND) U1.E9(GND) U1.E10(GND) U1.E11(GND) U1.F3(GND) U1.F4(GND) U1.F5(GND) U1.F9(GND) U1.F10(GND) U1.F11(GND) U1.G3(GND) U1.G4(GND) U1.G5(GND) U1.G9(GND) U1.G11(GND) U1.G12(GND) U1.G13(GND) U1.H3(GND) U1.H4(GND) U1.H5(GND) U1.J3(GND) U1.J4(GND) U1.J5(GND) U1.K3(GND) U1.K4(GND) U1.K5(GND) U1.K10(GND) U1.K11(GND) U1.L1(GND) U1.L2(GND) U1.L3(GND) U1.L4(GND) U1.L5(GND) U1.L6(GND) U1.L7(GND) U1.L14(GND) U1.L15(GND) U1.M1(GND) U1.M2(GND) U1.M3(GND) U1.M4(GND) U1.M5(GND) U1.M6(GND) U1.M7(GND) U1.M14(GND) U1.M15(GND) U1.N3(GND) U1.N4(GND) U1.N5(GND) U1.N8(GND) U1.N10(GND) U1.N11(GND) U1.N12(GND) U1.P3(GND) U1.P4(GND) U1.P5(GND) U1.P8(GND) U1.P9(GND) U1.P10(GND) U1.P11(GND) U1.P12(GND) U1.R3(GND) U1.R4(GND) U1.R5(GND) U1.R9(GND) U1.R11(GND) U1.R12(GND) U1.T3(GND) U1.T4(GND) U1.T5(GND) U1.T9(GND) U1.T10(GND) U1.T12(GND) U1.T13(GND) U1.U3(GND) U1.U4(GND) U1.U5(GND) U1.U9(GND) U1.U10(GND) U1.U11(GND) U1.V3(GND) U1.V4(GND) U1.V5(GND) U1.V10(GND) U1.V11(GND) U1.W3(GND) U1.W4(GND) U1.W5(GND) U1.W9(GND) U1.W10(GND) U1.W11(GND) U1.Y3(GND) U1.Y4(GND) U1.Y5(GND) U1.Y9(GND) U1.Y11(GND) U2.1(A0) U2.2(A1) U2.3(A2) U2.4(VSS) U2.7(WP)
GND_SIGNAL: C1.1 C2.1 C14.2 C15.2 E23.1(TP) E24.1(TP) JP1.3 JP2.3 JP3.3 R24.1 R26.1 R27.1 R28.1 R29.1 R30.1 R31.1 R33.2 U1.L10(SGND) U1.L11(SGND) U1.L12(SGND) U1.M10(SGND) U1.M11(SGND) U1.M12(SGND)
SVIN: R8.1 R9.2 U1.V9(SVIN)
VDD25: E16.1(TP) U1.G10(VDD25)
VDD33: E8.1(TP) Q3.2(S) R10.1 R11.1 R12.1 R13.1 R14.1 R15.1 R16.1 R18.1 R19.1 R94.1 R95.1 R106.1 U1.K9(VDD33)
VIN: CIN1.1 E4.1(TP) J10.1(TP) R9.1 R77.1 R82.1 R90.1 R91.1
VIN1: CIN2.1 CIN3.1 CIN4.1 CIN5.1 CIN6.1 CIN7.1 CIN8.1 CIN9.1 R90.2 R92.1 U1.A6(VIN1) U1.A7(VIN1) U1.A8(VIN1) U1.AA6(VIN0) U1.AA7(VIN0) U1.AA8(VIN0) U1.AB6(VIN0) U1.AB7(VIN0) U1.AB8(VIN0) U1.B6(VIN1) U1.B7(VIN1) U1.B8(VIN1) U1.C6(VIN1) U1.C7(VIN1) U1.C8(VIN1) U1.D6(VIN1) U1.D7(VIN1) U1.D8(VIN1) U1.E6(VIN1) U1.E7(VIN1) U1.E8(VIN1) U1.F6(VIN1) U1.F7(VIN1) U1.F8(VIN1) U1.G6(VIN1) U1.G7(VIN1) U1.G8(VIN1) U1.H6(VIN1) U1.H7(VIN1) U1.H8(VIN1) U1.J6(VIN1) U1.J7(VIN1) U1.K6(VIN1) U1.K7(VIN1) U1.N6(VIN0) U1.N7(VIN0) U1.P6(VIN0) U1.P7(VIN0) U1.R6(VIN0) U1.R7(VIN0) U1.R8(VIN0) U1.T6(VIN0) U1.T7(VIN0) U1.T8(VIN0) U1.U6(VIN0) U1.U7(VIN0) U1.U8(VIN0) U1.V6(VIN0) U1.V7(VIN0) U1.V8(VIN0) U1.W6(VIN0) U1.W7(VIN0) U1.W8(VIN0) U1.Y6(VIN0) U1.Y7(VIN0) U1.Y8(VIN0)
ALERTB: E10.1(TP) J1.6(ALERTB) J11.3(ALERTB) J12.3(ALERTB) R12.2 U1.J13(~{ALERT})
ASEL: R26.2 U1.H11(ASEL)
AUXVCC: C26.1 E21.1(A) J1.1(AUXP) J11.8(AUXP) J12.8(AUXP) R72.1 R73.1 U2.8(VCC)
COMP0a: C15.1 R41.1 U1.N13(COMP0a)
COMP0b: C14.1 R99.1 U1.M13(COMP0b)
COMP1a: C2.2 R41.2 U1.L8(COMP1a)
COMP1b: C1.2 R99.2 U1.L9(COMP1b)
EESCL: J1.11(AUXSCL) R72.2 U2.6(SCL)
EESDA: J1.12(AUXSDA) R73.2 U2.5(SDA)
FAULT0: D2.2(ANODE) E13.1(TP) R15.2 R35.2 R63.2 R64.2 U1.H13(~{FAULT0})
FAULT1: D1.2(ANODE) E14.1(TP) R16.2 R35.1 R61.2 R62.2 U1.H12(~{FAULT1})
FSWPH_CFG: R27.2 U1.J11(FSWPH_CFG)
INTVCC: E3.1(TP) R8.2 U1.R10(INTVCC)
PGOOD0: E26.1(TP) R18.2 R96.2 U1.R14(PGOOD0)
PGOOD1: E25.1(TP) R19.2 R96.1 U1.N9(PGOOD1)
RUN0: D2.1(CATHODE) E18.1(A) JP1.2 R38.2 R62.1 R65.2 R70.2 R89.2 U1.J12(RUN0)
RUN1: D1.1(CATHODE) E19.1(A) JP2.2 R38.1 R64.1 R68.2 R69.2 R88.2 U1.K12(RUN1)
RUNP: JP3.2 U1.Y10(RUNP)
SCL: E11.1(TP) J1.4(SCL) J11.6(SCL) J12.6(SCL) R13.2 U1.J14(SCL)
SDA: E12.1(TP) J1.2(SDA) J11.4(SDA) J12.4(SDA) R14.2 U1.H14(SDA)
SHARE_CLK: E6.1(TP) R11.2 R66.1 U1.K8(SHARE_CLK)
SYNC: E9.1(TP) R10.2 R67.1 U1.K14(SYNC)
VOSNS0+: C16.1 E15.1(TP) R25.1 R97.1 U1.P14(VOSNS0+)
VOSNS0-: C16.2 E17.1(TP) R32.1 R98.1 U1.N14(VOSNS0-)
VOSNS1+: C17.1 E1.1(TP) R93.2 R97.2 U1.M9(VOSNS1+)
VOSNS1-: C17.2 E7.1(TP) R3.1 R98.2 U1.M8(VOSNS1-)
VOUT0: C21.1 COUT5.1 COUT6.1 COUT7.1 COUT8.1 COUT9.1 COUT14.1 COUT15.1 COUT16.1 COUT22.1 J2.1 J7.1(TP) R25.2 R48.1 R50.2 R100.1 R101.1 R102.1 R103.1 U1.AA12(VOUT0) U1.AA13(VOUT0) U1.AA14(VOUT0) U1.AA15(VOUT0) U1.AB12(VOUT0) U1.AB13(VOUT0) U1.AB14(VOUT0) U1.AB15(VOUT0) U1.N15(VOUT0) U1.P15(VOUT0) U1.R15(VOUT0) U1.T15(VOUT0) U1.U12(VOUT0) U1.U13(VOUT0) U1.U14(VOUT0) U1.U15(VOUT0) U1.V12(VOUT0) U1.V13(VOUT0) U1.V14(VOUT0) U1.V15(VOUT0) U1.W12(VOUT0) U1.W13(VOUT0) U1.W14(VOUT0) U1.W15(VOUT0) U1.Y12(VOUT0) U1.Y13(VOUT0) U1.Y14(VOUT0) U1.Y15(VOUT0)
VOUT0_CFG: R30.2 U1.J10(VOUT0_CFG)
VOUT1: C22.1 COUT1.1 COUT2.1 COUT3.1 COUT4.1 COUT10.1 COUT18.1 COUT19.1 COUT20.1 COUT21.1 J3.1 J6.1(TP) R49.1 R51.2 R93.1 R100.2 R101.2 R102.2 R103.2 U1.A12(VOUT1) U1.A13(VOUT1) U1.A14(VOUT1) U1.A15(VOUT1) U1.B12(VOUT1) U1.B13(VOUT1) U1.B14(VOUT1) U1.B15(VOUT1) U1.C12(VOUT1) U1.C13(VOUT1) U1.C14(VOUT1) U1.C15(VOUT1) U1.D12(VOUT1) U1.D13(VOUT1) U1.D14(VOUT1) U1.D15(VOUT1) U1.E12(VOUT1) U1.E13(VOUT1) U1.E14(VOUT1) U1.E15(VOUT1) U1.F12(VOUT1) U1.F13(VOUT1) U1.F14(VOUT1) U1.F15(VOUT1) U1.G15(VOUT1) U1.H15(VOUT1) U1.J15(VOUT1) U1.K15(VOUT1)
VOUT1_CFG: R31.2 U1.H10(VOUT1_CFG)
VTRIM0_CFG: R29.2 U1.J9(VTRIM0_CFG)
VTRIM1_CFG: R28.2 U1.H9(VTRIM1_CFG)
N16779111: J4.1 Q1.3(SOURCE) Q2.3(SOURCE) R53.2
N16779469: C23.1 C24.1 Q1.2(DRAIN) Q1.4(DRAIN) Q2.2(DRAIN) Q2.4(DRAIN) R48.2 R49.2
N17166430: P1.1(TP) R105.2 U1.A1(SW1) U1.A2(SW1) U1.B1(SW1) U1.B2(SW1) U1.C1(SW1) U1.C2(SW1) U1.D1(SW1) U1.D2(SW1) U1.E1(SW1) U1.E2(SW1) U1.F1(SW1) U1.F2(SW1) U1.G1(SW1) U1.G2(SW1) U1.H1(SW1) U1.H2(SW1) U1.J1(SW1) U1.J2(SW1) U1.K1(SW1) U1.K2(SW1)
N17583721: E20.1(TP) Q1.1(GATE) Q2.1(GATE) R52.1
N18333697: J11.1(FAULTB) J12.1(FAULTB) R61.1 R63.1
N18333715: J1.8(OUTEN_0) R74.1
N18333717: J1.9(OUTEN_1) R75.1
N18333729: J11.2(CTRL) J12.2(CTRL) R65.1 R68.1 R74.2 R75.2
N18333815: Q3.1(G) R77.2 R78.1
N18333849: J11.5(SHARE_CLK) J12.5(SHARE_CLK) R66.2
N18333851: J11.7(RESETB) J12.7(RESETB)
N18333853: J11.9(UNUSED) J12.9(UNUSED) R67.2 R88.1 R89.1
N18333865: J11.13(12V) J11.14(12V) J12.13(12V) J12.14(12V) R82.2
N18333941: J11.10(UNUSED) J12.10(UNUSED) R83.2
N18377354: U1.G14(TSNS1B) U1.L13(TSNS1A)
N18377395: U1.K13(TSNS0A) U1.T14(TSNS0B)
N18421268: JP2.1 R95.2
N18437001: P2.1(TP) R104.2 U1.AA1(SW0) U1.AA2(SW0) U1.AB1(SW0) U1.AB2(SW0) U1.N1(SW0) U1.N2(SW0) U1.P1(SW0) U1.P2(SW0) U1.R1(SW0) U1.R2(SW0) U1.T1(SW0) U1.T2(SW0) U1.U1(SW0) U1.U2(SW0) U1.V1(SW0) U1.V2(SW0) U1.W1(SW0) U1.W2(SW0) U1.Y1(SW0) U1.Y2(SW0)
N18440006: C29.1 R91.2 U1.R13(IN+)
N18440037: C29.2 R92.2 U1.P13(IN-)
N18449385: R24.2 U1.J8(WP)
N18450678: JP1.1 R94.2
N18468612: C31.1 R104.1
N18469531: C32.1 R105.1
N18488437: JP3.1 R106.2
N18576190: C33.1 U1.T11(VBIAS)
N18598201: C27.1 R69.1
N18598202: C28.1 R70.1

Not connected (* = marked no-connect by the designer): J1 7(GPIO_1)

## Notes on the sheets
sheet 1
- 1.5V/50A
- 0.035 VIA
- TESTPOINTS
- 4.5V - 16V
- 25V
- ON
- OFF
- ON
- OFF
- ON
- OFF
- 1.0V/50A
- *
- NOTE: UNLESS OTHERWISE SPECIFIED
- ASSY
- R28,R35,R38,R41,R96,R97,R98,R99
- R100,R101,R102,R103
- R93, R3
- C2
- R31
- 1.  ALL RESISTORS AND CAP ARE 0603.
- 2.  WHEN VIN < 5.75V, SHORT INTVCC TO SVIN WITH R8=0 OHM
- -A
- OPT
- OPT
- 10 OHM
- 6.8nF
- 4.22K
- WITH DIGITAL POWER MANAGEMENT
- -B
- 0 OHM
- 0 OHM
- OPT
- OPT
- 2.43K
sheet 2
- ALL PARTS ON THIS PAGE ARE FOR DEMO BOARD ONLY, NOT NEEDED IN CUSTOMER DESIGN
- TO DC1613A
- 1206
- PSM STACKING CONNECTORS:
  J12, FEMALE, CONN RECEPT 2MM DUAL R/A 14POS, Sullins Conn. NPPN072FJFN-RC
  J11, MALE, CONN HEADER 14POS 2MM R/A GOLD, Molex Connector Corp. 87760-1416
- OPTIONAL CIRCUIT FOR PROGRAMMING
  WITHOUT VIN
- WITH DIGITAL POWER MANAGEMENT
- WITH DIGITAL POWER MANAGEMENT
- WITH DIGITAL POWER MANAGEMENT
- 05-07-18
sheet 3
- ALL PARTS ON THIS PAGE ARE FOR DEMO ONLY, NOT NEEDED IN CUSTOMER DESIGN
- DYNAMIC LOAD CIRCUIT
- VOUT1
- 2512
- 2512
- BLEEDER LOADS
- DO NOT EXCEED 5% DUTY CYCLE!
- 2010
- OPTIONAL JUMPER FOR DUAL PHASE SINGLE OUTPUT CONFIGURATION
- WITH DIGITAL POWER MANAGEMENT
- WITH DIGITAL POWER MANAGEMENT
- WITH DIGITAL POWER MANAGEMENT
- WITH DIGITAL POWER MANAGEMENT
- 05-07-18
